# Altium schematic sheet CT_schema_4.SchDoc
size 278 x 236 mm
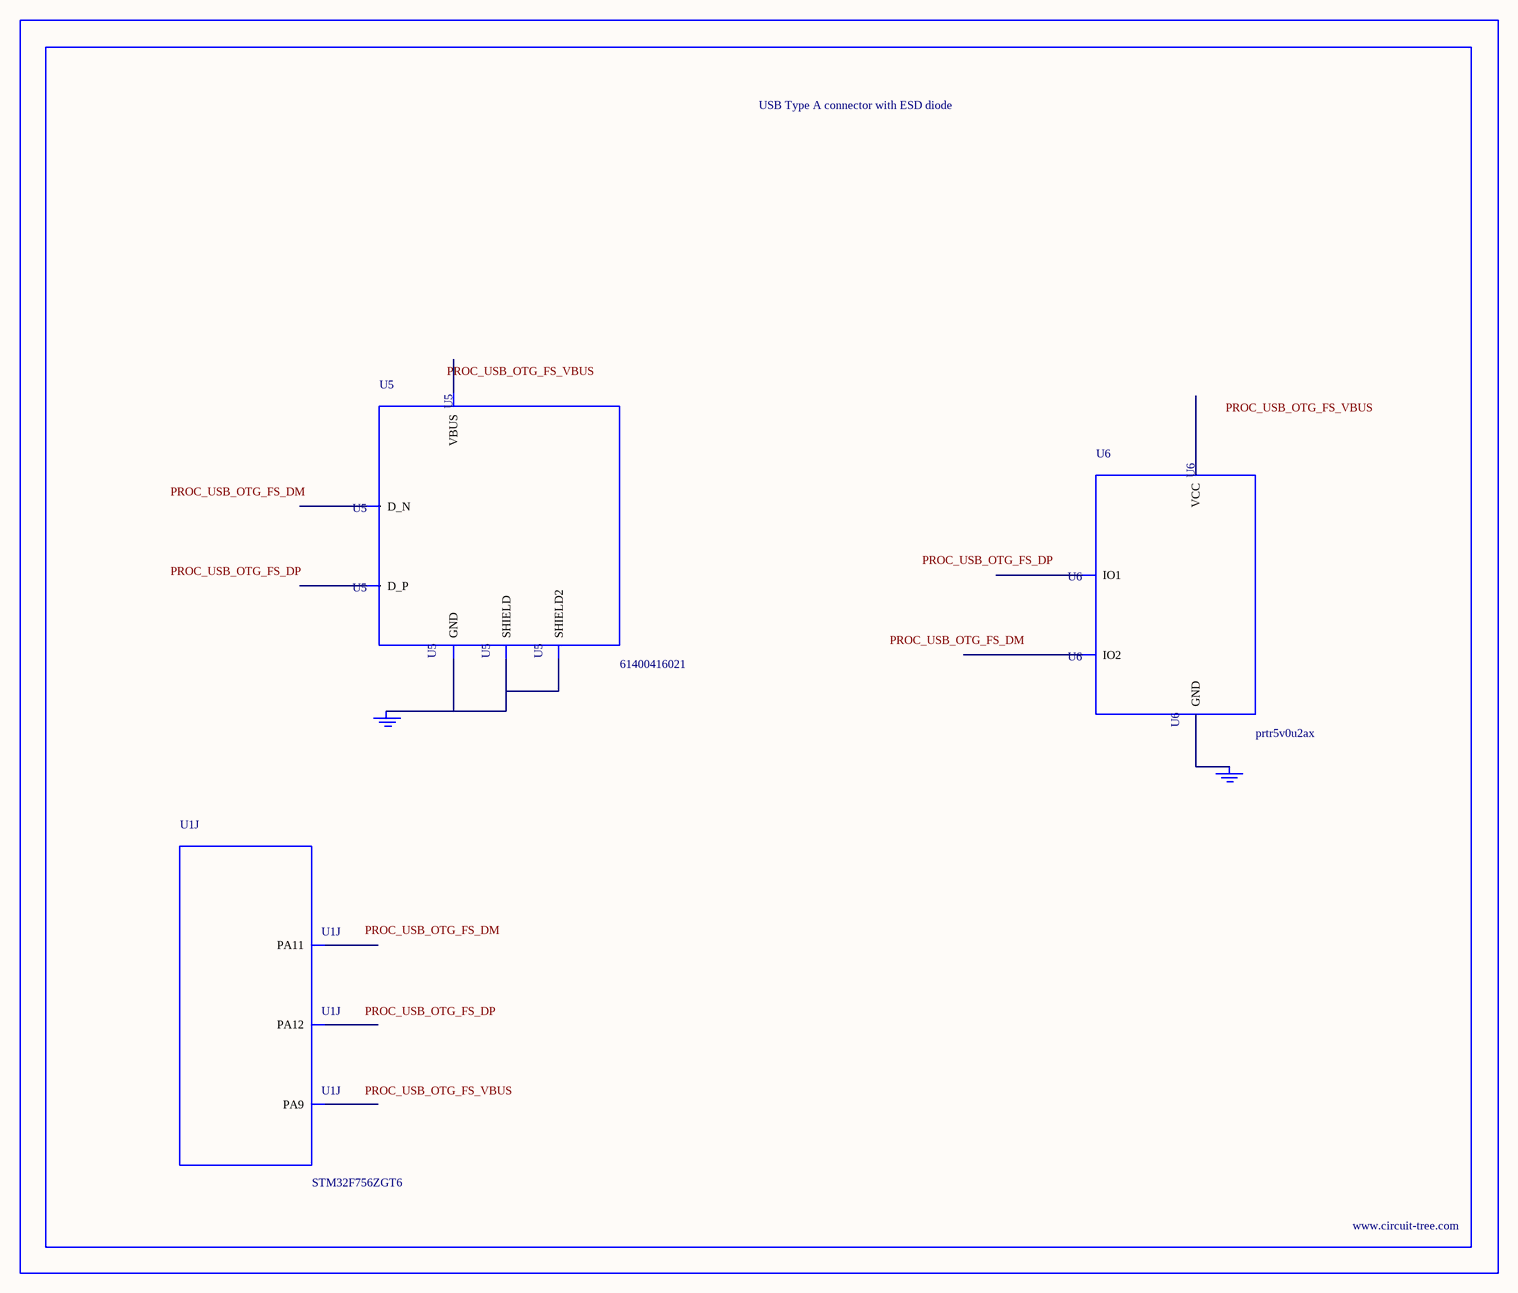
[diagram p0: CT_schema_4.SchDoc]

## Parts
BORDER3  (no value)
GND_INSTANCE_3_0  (no value)
GND_INSTANCE_3_1  (no value)
U1  STM32F756ZGT6  [LQFP144]  (part J of 11)
U5  61400416021  [USB-A-H]
U6  prtr5v0u2ax  [SOT143B]

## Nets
NetGND_INSTANCE_3_0_0: GND_INSTANCE_3_0.0(GND) U5.4(GND) U5.5(SHIELD) U5.6(SHIELD2)
NetGND_INSTANCE_3_1_0: GND_INSTANCE_3_1.0(GND) U6.1(GND)

Not connected (* = marked no-connect by the designer): U1 101(PA9) 103(PA11) 104(PA12); U5 1(VBUS) 2(D_N) 3(D_P); U6 2(IO1) 3(IO2) 4(VCC)

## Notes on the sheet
- Labels drawn without touching a wire or pin: PROC_USB_OTG_FS_DM, PROC_USB_OTG_FS_DP, PROC_USB_OTG_FS_VBUS

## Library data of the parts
BORDER3 = BORDER_PAGE3
GND_INSTANCE_3_0 GND_INSTANCE_3_1 = GND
